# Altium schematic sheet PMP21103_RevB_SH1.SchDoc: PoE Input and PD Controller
size 431 x 279 mm; Date: Not shown in title block; ApprovedBy: Not shown in title block; CheckedBy: Not shown in title block; Author: Not shown in title block; CompanyName: Not shown in title block; Engineer: Not shown in title block; Organization: Not shown in title block; Address1: Not shown in title block; Address2: Not shown in title block; Address3: Not shown in title block; Address4: Not shown in title block; DocumentNumber: 1; Revision: Use project parameter SCH_Rev; SheetNumber: 1; SheetTotal: 3; PageSetup: Record=PageOptions¦CenterHorizontal=True¦CenterVertical=True¦PrintScale=1.00¦XCorrection=1.00¦YCorrection=1.00¦PrintKind=0¦BorderSize=5000000¦LeftOffset=0¦BottomOffset=0¦Orientation=2¦PaperLength=1000¦PaperWidth=1000¦Scale=100¦PaperSource=15¦PrintQuality=600¦MediaType=1¦DitherType=10¦PaperKind=Letter¦PrintScaleMode=1
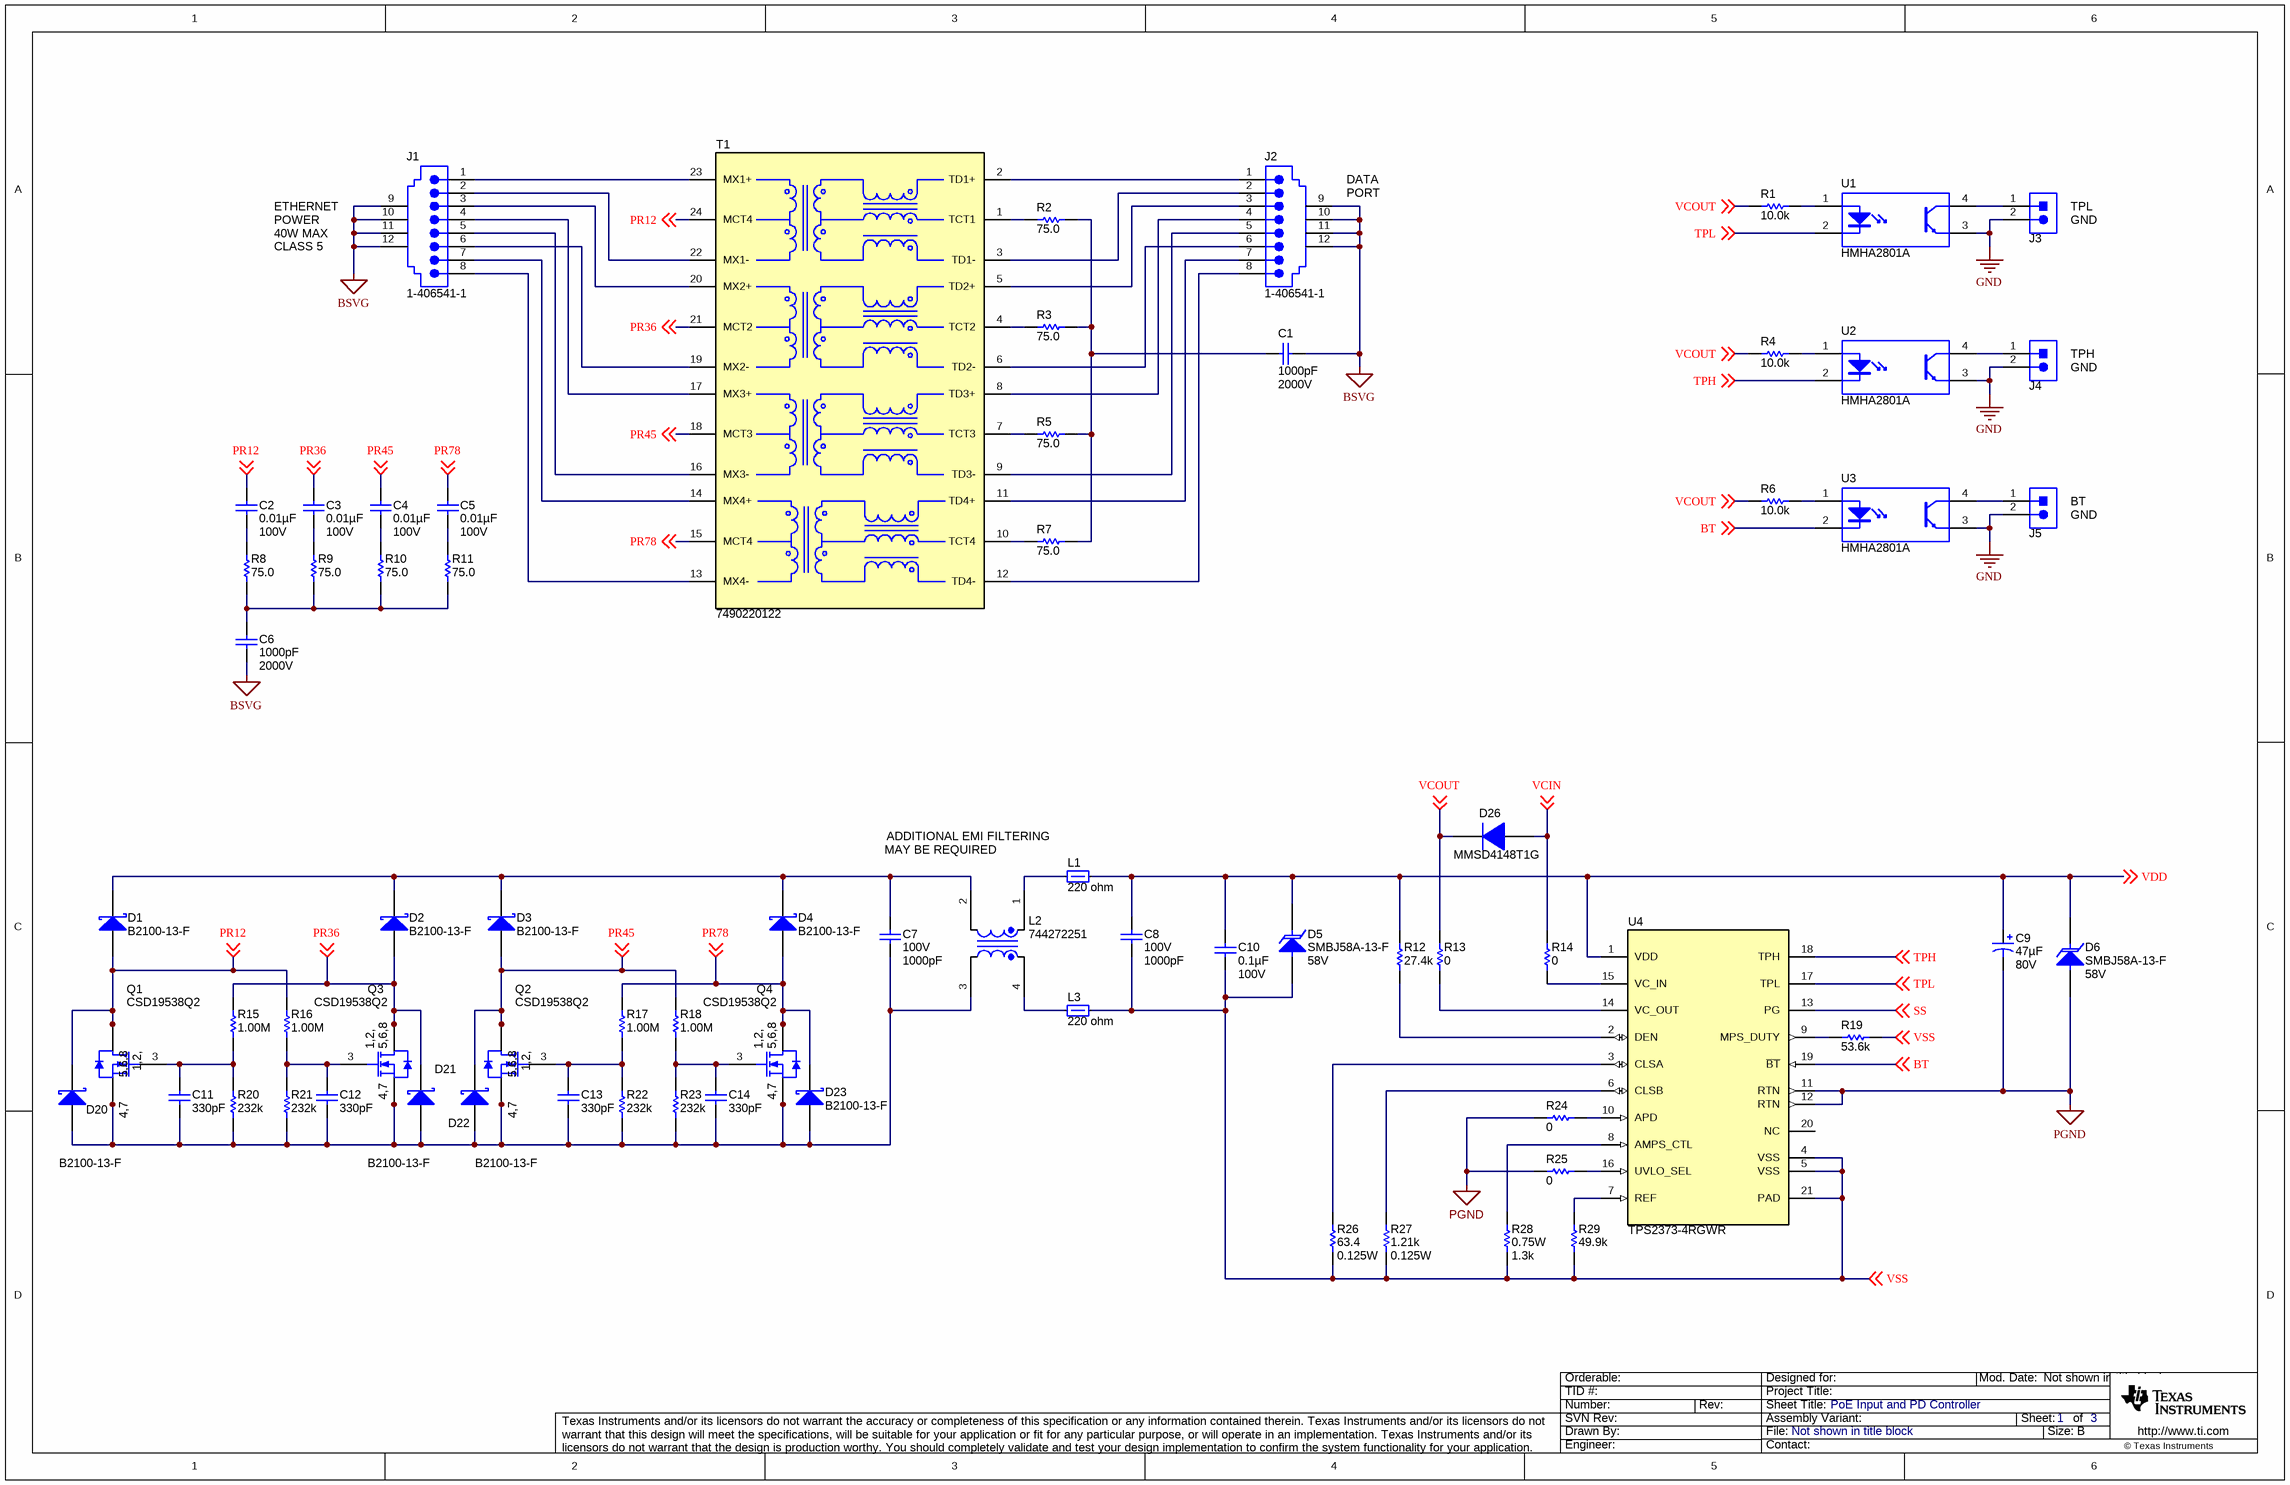
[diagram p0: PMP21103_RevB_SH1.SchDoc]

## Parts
C1  ValueDisplayed: 1000pF  Value2: 2000V  [1812]  (hidden comment: GR443QR73D102KW01L)
C2  ValueDisplayed: 0.01µF  Value2: 100V  [0603L]  (hidden comment: GRM188R72A103KA01D)
C3  ValueDisplayed: 0.01µF  Value2: 100V  [0603L]  (hidden comment: GRM188R72A103KA01D)
C4  ValueDisplayed: 0.01µF  Value2: 100V  [0603L]  (hidden comment: GRM188R72A103KA01D)
C5  ValueDisplayed: 0.01µF  Value2: 100V  [0603L]  (hidden comment: GRM188R72A103KA01D)
C6  ValueDisplayed: 1000pF  Value2: 2000V  [1812]  (hidden comment: GR443QR73D102KW01L)
C7  VDC_V: 100V  ValueDisplayed: 1000pF  [0603]  (hidden comment: GRM188R72A102KA01D)
C8  VDC_V: 100V  ValueDisplayed: 1000pF  [0603]  (hidden comment: GRM188R72A102KA01D)
C9  ValueDisplayed: 47µF  Value2: 80V  [SM_RADIAL_G]  (hidden comment: EEE-FK1K470P)
C10  ValueDisplayed: 0.1µF  Value2: 100V  [0805_HV]  (hidden comment: C2012X7R2A104K125AA)
C11  ValueDisplayed: 330pF  [0603L]  (hidden comment: GRM1885C1H331JA01D)
C12  ValueDisplayed: 330pF  [0603L]  (hidden comment: GRM1885C1H331JA01D)
C13  ValueDisplayed: 330pF  [0603L]  (hidden comment: GRM1885C1H331JA01D)
C14  ValueDisplayed: 330pF  [0603L]  (hidden comment: GRM1885C1H331JA01D)
D1  B2100-13-F  [SMB]
D2  B2100-13-F  [SMB]
D3  B2100-13-F  [SMB]
D4  B2100-13-F  [SMB]
D5  SMBJ58A-13-F  value 58V  [SMB]
D6  SMBJ58A-13-F  value 58V  [SMB]
D20  B2100-13-F  [SMB]
D21  B2100-13-F  [SMB]
D22  B2100-13-F  [SMB]
D23  B2100-13-F  [SMB]
D26  MMSD4148T1G  [SOD-123]
J1  1-406541-1  [TEC_1-406541-1]
J2  1-406541-1  [TEC_1-406541-1]
J3  PEC02SAAN  [CONN_PEC02SAAN]  (value not drawn)
J4  PEC02SAAN  [CONN_PEC02SAAN]  (value not drawn)
J5  PEC02SAAN  [CONN_PEC02SAAN]  (value not drawn)
L1  value 220 ohm  [0603]  (hidden comment: MPZ1608S221A)
L2  744272251  [WE-SL5]
L3  value 220 ohm  [0603]  (hidden comment: MPZ1608S221A)
Q1  CSD19538Q2  [DQK0006C]
Q2  CSD19538Q2  [DQK0006C]
Q3  CSD19538Q2  [DQK0006C]
Q4  CSD19538Q2  [DQK0006C]
R1  ValueDisplayed: 10.0k  [0603L]  (hidden comment: CRCW060310K0FKEA)
R2  value 75.0  [0603L]  (hidden comment: CRCW060375R0FKEA)
R3  value 75.0  [0603L]  (hidden comment: CRCW060375R0FKEA)
R4  ValueDisplayed: 10.0k  [0603L]  (hidden comment: CRCW060310K0FKEA)
R5  value 75.0  [0603L]  (hidden comment: CRCW060375R0FKEA)
R6  ValueDisplayed: 10.0k  [0603L]  (hidden comment: CRCW060310K0FKEA)
R7  value 75.0  [0603L]  (hidden comment: CRCW060375R0FKEA)
R8  value 75.0  [0603L]  (hidden comment: CRCW060375R0FKEA)
R9  value 75.0  [0603L]  (hidden comment: CRCW060375R0FKEA)
R10  value 75.0  [0603L]  (hidden comment: CRCW060375R0FKEA)
R11  value 75.0  [0603L]  (hidden comment: CRCW060375R0FKEA)
R12  ValueDisplayed: 27.4k  [0603L]  (hidden comment: CRCW060327K4FKEA)
R13  ValueDisplayed: 0  [0603L]  (hidden comment: CRCW06030000Z0EA)
R14  ValueDisplayed: 0  [0603L]  (hidden comment: CRCW06030000Z0EA)
R15  ValueDisplayed: 1.00M  [0603L]  (hidden comment: CRCW06031M00FKEA)
R16  ValueDisplayed: 1.00M  [0603L]  (hidden comment: CRCW06031M00FKEA)
R17  ValueDisplayed: 1.00M  [0603L]  (hidden comment: CRCW06031M00FKEA)
R18  ValueDisplayed: 1.00M  [0603L]  (hidden comment: CRCW06031M00FKEA)
R19  ValueDisplayed: 53.6k  [0603L]  (hidden comment: CRCW060353K6FKEA)
R20  ValueDisplayed: 232k  [0603L]  (hidden comment: CRCW0603232KFKEA)
R21  ValueDisplayed: 232k  [0603L]  (hidden comment: CRCW0603232KFKEA)
R22  ValueDisplayed: 232k  [0603L]  (hidden comment: CRCW0603232KFKEA)
R23  ValueDisplayed: 232k  [0603L]  (hidden comment: CRCW0603232KFKEA)
R24  ValueDisplayed: 0  [0603L]  (hidden comment: CRCW06030000Z0EA)
R25  ValueDisplayed: 0  [0603L]  (hidden comment: CRCW06030000Z0EA)
R26  ValueDisplayed: 63.4  Value2: 0.125W  [0805L]  (hidden comment: CRCW080563R4FKEA)
R27  ValueDisplayed: 1.21k  Value2: 0.125W  [0805L]  (hidden comment: CRCW08051K21FKEA)
R28  Value2: 0.75W  ValueDisplayed: 1.3k  [2010]  (hidden comment: CRCW20101K30JNEF)
R29  ValueDisplayed: 49.9k  [0603L]  (hidden comment: CRCW060349K9FKEA)
T1  7490220122  [Wurth_7490220122]
U1  HMHA2801A  [MFP04A]
U2  HMHA2801A  [MFP04A]
U3  HMHA2801A  [MFP04A]
U4  TPS2373-4RGWR  [RGW0020B]

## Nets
BSVG: C1.1 C6.2 J1.9 J1.10 J1.11 J1.12 J2.9 J2.10 J2.11 J2.12
GND: J3.2 J4.2 J5.2 U1.3(E) U2.3(E) U3.3(E)
PGND: C9.2(-) D6.2(A) R24.1 R25.2 U4.11(RTN) U4.12(RTN)
BT: U3.2(K) U4.19(~{BT}) ; off-sheet BT
PR12: C2.1 D1.2(A) D20.1(K) Q1.1(D) Q1.2(D) Q1.5(D) Q1.6(D) Q1.8(D) R16.1 T1.24(MCT4) ; off-sheet PR12
PR36: C3.1 D2.2(A) D21.1(K) Q3.1(D) Q3.2(D) Q3.5(D) Q3.6(D) Q3.8(D) R15.1 T1.21(MCT2) ; off-sheet PR36
PR45: C4.1 D3.2(A) D22.1(K) Q2.1(D) Q2.2(D) Q2.5(D) Q2.6(D) Q2.8(D) R18.1 T1.18(MCT3) ; off-sheet PR45
PR78: C5.1 D4.2(A) D23.1(K) Q4.1(D) Q4.2(D) Q4.5(D) Q4.6(D) Q4.8(D) R17.1 T1.15(MCT4) ; off-sheet PR78
SS: U4.13(PG) ; off-sheet SS
TPH: U2.2(K) U4.18(TPH) ; off-sheet TPH
TPL: U1.2(K) U4.17(TPL) ; off-sheet TPL
VCIN: D26.2(A) R14.2 ; off-sheet VCIN
VCOUT: D26.1(K) R1.1 R4.1 R6.1 R13.2 ; off-sheet VCOUT
VDD: C8.1 C9.1(+) C10.2 D5.1(K) D6.1(K) L1.2 R12.2 U4.1(VDD) ; off-sheet VDD
VSS: C8.2 C10.1 D5.2(A) L3.2 R19.2 R26.1 R27.1 R28.1 R29.1 U4.4(VSS) U4.5(VSS) U4.21(PAD) ; off-sheet VSS
NetC1_2: C1.2 R2.1 R3.1 R5.1 R7.1
NetC2_2: C2.2 R8.2
NetC3_2: C3.2 R9.2
NetC4_2: C4.2 R10.2
NetC5_2: C5.2 R11.2
NetC6_1: C6.1 R8.1 R9.1 R10.1 R11.1
NetC7_1: C7.1 D1.1(K) D2.1(K) D3.1(K) D4.1(K) L2.2
NetC7_2: C7.2 C11.2 C12.2 C13.2 C14.2 D20.2(A) D21.2(A) D22.2(A) D23.2(A) L2.3 Q1.4(S) Q1.7(S) Q2.4(S) Q2.7(S) Q3.4(S) Q3.7(S) Q4.4(S) Q4.7(S) R20.1 R21.1 R22.1 R23.1
NetC11_1: C11.1 Q1.3(G) R15.2 R20.2
NetC12_1: C12.1 Q3.3(G) R16.2 R21.2
NetC13_1: C13.1 Q2.3(G) R17.2 R22.2
NetC14_1: C14.1 Q4.3(G) R18.2 R23.2
NetJ1_1: J1.1 T1.23(MX1+)
NetJ1_2: J1.2 T1.22(MX1-)
NetJ1_3: J1.3 T1.20(MX2+)
NetJ1_4: J1.4 T1.17(MX3+)
NetJ1_5: J1.5 T1.16(MX3-)
NetJ1_6: J1.6 T1.19(MX2-)
NetJ1_7: J1.7 T1.14(MX4+)
NetJ1_8: J1.8 T1.13(MX4-)
NetJ2_1: J2.1 T1.2(TD1+)
NetJ2_2: J2.2 T1.3(TD1-)
NetJ2_3: J2.3 T1.5(TD2+)
NetJ2_4: J2.4 T1.8(TD3+)
NetJ2_5: J2.5 T1.9(TD3-)
NetJ2_6: J2.6 T1.6(TD2-)
NetJ2_7: J2.7 T1.11(TD4+)
NetJ2_8: J2.8 T1.12(TD4-)
NetJ3_1: J3.1 U1.4(C)
NetJ4_1: J4.1 U2.4(C)
NetJ5_1: J5.1 U3.4(C)
NetL1_1: L1.1 L2.1
NetL2_4: L2.4 L3.1
NetR1_2: R1.2 U1.1(A)
NetR2_2: R2.2 T1.1(TCT1)
NetR3_2: R3.2 T1.4(TCT2)
NetR4_2: R4.2 U2.1(A)
NetR5_2: R5.2 T1.7(TCT3)
NetR6_2: R6.2 U3.1(A)
NetR7_2: R7.2 T1.10(TCT4)
NetR12_1: R12.1 U4.2(DEN)
NetR13_1: R13.1 U4.14(VC_OUT)
NetR14_1: R14.1 U4.15(VC_IN)
NetR19_1: R19.1 U4.9(MPS_DUTY)
NetR24_2: R24.2 U4.10(APD)
NetR25_1: R25.1 U4.16(UVLO_SEL)
NetR26_2: R26.2 U4.3(CLSA)
NetR27_2: R27.2 U4.6(CLSB)
NetR28_2: R28.2 U4.8(AMPS_CTL)
NetR29_2: R29.2 U4.7(REF)

Not connected (* = marked no-connect by the designer): U4 20(NC)

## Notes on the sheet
- ETHERNET
- 40W MAX
- POWER
- (near J2) DATA
- (near J2) PORT
- (near J3) TPL
- (near J3) GND
- CLASS 5
- (near J4) TPH
- (near J4) GND
- (near J5) BT
- (near J5) GND
- (near L1) ADDITIONAL EMI FILTERING
- MAY BE REQUIRED

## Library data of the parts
C1 C6 = GR443QR73D102KW01L: CAP, CERM, 1000 pF, 2000 V, +/- 10%, X7R, 1812; Manufacturer: MuRata; Polarized: N; CompType: Capacitor; Value: 1000pF; U/M: EA; Cap_F: 0.000000001; Tolerance_%: 10; Value1: Unknown; VDC_V: 2000; TaMin_C: -55; TaMax_C: 125; SizeArea_mm2: 14.4; SizeAreaWB_mm2: 23.1; SizeX_mm: 4.5; SizeY_mm: 3.2; SizeZ_mm: 1.35; AEC Category: Q200
C2-C5 = GRM188R72A103KA01D: CAP, CERM, 0.01 µF, 100 V, +/- 10%, X7R, 0603; Manufacturer: MuRata; Polarized: N; CompType: Capacitor; Value: 0.01uF; U/M: EA; Cap_F: 0.00000001; Tolerance_%: 10; Value1: Unknown; VDC_V: 100; TaMin_C: -55; TaMax_C: 125; Cap_Case: 0603; SizeArea_mm2: 1.28; SizeAreaWB_mm2: 4.68; SizeX_mm: 1.6; SizeY_mm: 0.8; SizeZ_mm: 1; AEC Category: Q200
C7 C8 = CMP-0007467-2: CAP, CERM, 1000 pF, 100 V, +/- 10%, X7R, 0603; Manufacturer: MuRata; TaMin_C: -55°C; Polarized: N; SizeAreaWB_mm2: 4.68; Value1: Unknown; U/M: EA; Value: 1000pF; TaMax_C: 125°C; SizeZ_mm: 1; SizeX_mm: 1.6; SizeY_mm: 0.8; SizeArea_mm2: 1.28; Cap_F: 1nF; AEC Category: Q200
C9 = EEE-FK1K470P: CAP, AL, 47 µF, 80 V, +/- 20%, 0.7 ohm, AEC-Q200 Grade 2, SMD; Manufacturer: Panasonic; Polarized: Y; CompType: Capacitor; Value: 47uF; U/M: EA; Cap_F: 0.000047; Tolerance_%: 20; Value1: 0.7 ohm; VDC_V: 80; ESR_ohm: 0.7; IRMS_A: 0.2; TaMin_C: -55; TaMax_C: 105; Cap_Case: G; AEC Category: Q200; AEC Grade: 2; SizeAreaWB_mm2: 172.2; SizeArea_mm2: 123.6; SizeX_mm: 12; SizeY_mm: 10.3; SizeZ_mm: 10.2
C10 = C2012X7R2A104K125AA: CAP, CERM, 0.1 µF, 100 V, +/- 10%, X7R, 0805; Manufacturer: TDK; Polarized: N; CompType: Capacitor; Value: 0.1uF; U/M: EA; Cap_F: 0.0000001; Tolerance_%: 10; ESR_ohm: 0.020726; Value1: 0.020726 ohm; VDC_V: 100; IRMS_A: 1.456; TaMin_C: -55; TaMax_C: 125; Cap_Case: 0805; SizeArea_mm2: 2.5; SizeAreaWB_mm2: 6.75; SizeX_mm: 2; SizeY_mm: 1.25; SizeZ_mm: 1.45; AEC Category: Q200
C11-C14 = GRM1885C1H331JA01D: CAP, CERM, 330 pF, 50 V, +/- 5%, C0G/NP0, 0603; Manufacturer: MuRata; Polarized: N; CompType: Capacitor; Value: 330pF; U/M: EA; Cap_F: 0.00000000033; Tolerance_%: 5; Value1: Unknown; VDC_V: 50; Value2: 50V; TaMin_C: -55; TaMax_C: 125; Cap_Case: 0603; SizeArea_mm2: 1.28; SizeAreaWB_mm2: 4.68; SizeX_mm: 1.6; SizeY_mm: 0.8; SizeZ_mm: 1; AEC Category: Q200
D1-D4 = B2100-13-F: Diode, Schottky, 100V, 2A, SMB; Manufacturer: Diodes Inc.; U/M: EA; Vf_V: 0.79; Value2: 0.79V; Io_A: 2; Vr_V: 100; TJmax_C: 150; RJC_CperW: 15
D5 D6 = SMBJ58A-13-F: Diode, TVS, Uni, 58V, 600W, SMB; Manufacturer: Diodes Inc.; U/M: EA; Power_W: 5; Vr_V: 58; Value1: 5W
D20-D23 = CMP-0028397-2: Diode, Schottky, 100 V, 2 A, SMB; Manufacturer: Diodes Inc.; Value2: 0.79V; Value1: 2A; SizeArea_mm2: 21.336; Value: 100V; Green_REACh: Passed; Green_Lifecycle: Active; Vf_V: 790mV; SizeY_mm: 3.81; AEC Category: Q101; SizeZ_mm: 2.6; TJmax_C: 150°C; RJC_CperW: 15; SizeAreaWB_mm2: 44.156; SizeX_mm: 5.6
D26 = CMP-0029032-2: Diode, Switching, 100 V, 0.2 A, SOD-123; Manufacturer: ON Semiconductor; Value: 100V; SizeY_mm: 1.7; Io_A: 200mA; SizeAreaWB_mm2: 13.095; SizeArea_mm2: 6.545; Vf_V: 1V; TJmax_C: 150°C; SizeX_mm: 3.85; SizeZ_mm: 1.35; Value1: 0.2A; Green_Lifecycle: Active; AEC Category: Q101; Green_REACh: Passed
J1 J2 = 1-406541-1: RJ-45, Right Angle, No LED, tab up; Manufacturer: AMP; SymbolCreator: x0208326; CompType: Connector; U/M: EA; Note: updated F/S per request.  Made footprint to max size.  2103-11-27
J3-J5 = PEC02SAAN: Header, 100mil, 2x1, Tin, TH; Manufacturer: Sullins Connector Solutions; SymbolCreator: a0412235; U/M: EA
L1 L3 = MPZ1608S221A: Ferrite Bead, 220 ohm @ 100 MHz, 2.2 A, 0603; Manufacturer: TDK; Imax_A: 2.2; DCR_ohm: 0.05; Value1: 0.05 ohm; Value2: 2.2A; ZTyp@100MHz_Ohm: 220
L2 = 744272251: Coupled inductor, 250 µH,  A, 0.035 ohm, SMD; Manufacturer: Wurth Elektronik; SymbolCreator: a0412235; ValueDisplayed: 250µH; Value: 250uH; Ind_H: 250.0E-6; DCR_ohm: 0.035
Q1-Q4 = CSD19538Q2: MOSFET, N-CH, 100 V, 4.5 A, DQK0006C (WSON-6); Manufacturer: Texas Instruments; Alternate Manufacturer: None; U/M: EA; ChType: N; Value: 100V; VdsMax_V: 100; Value1: ? ohm; Value2: ? nC; Vgs_V: 20; IdsMax_A: 4.5; SizeAreaWB_mm2: 9; SizeArea_mm2: 4; SizeX_mm: 2; SizeZ_mm: 0.8; AEC Category: Q101
R1 R4 R6 = CRCW060310K0FKEA: RES, 10.0 k, 1%, 0.1 W, 0603; Manufacturer: Vishay-Dale; CompType: Resistor; Value: 10.0k; Res_ohm: 10000; Value_Code: 10k0; Tolerance_%: 1; Power_W: 0.1; Value2: 0.1W; VDC_V: 75; TempCo: 100 ppm/C; EIA_Code: E96; U/M: EA
R2 R3 R5 R7-R11 = CRCW060375R0FKEA: RES, 75.0 ohm, 1%, 0.1W, 0603; Manufacturer: Vishay-Dale; CompType: Resistor; Res_ohm: 75; Value_Code: 75R0; Tolerance_%: 1; Power_W: 0.1; TempCo: 100 ppm/C; EIA_Code: E96; U/M: EA
R12 = CRCW060327K4FKEA: RES, 27.4 k, 1%, 0.1 W, 0603; Manufacturer: Vishay-Dale; CompType: Resistor; Value: 27.4k; Res_ohm: 27400; Value_Code: 27k4; Tolerance_%: 1; Power_W: 0.1; Value2: 0.1W; VDC_V: 75; TempCo: 100 ppm/C; EIA_Code: E96; U/M: EA; SizeArea_mm2: 1.28; SizeX_mm: 1.6; SizeY_mm: 0.8; AEC Category: Q200; Green_Lifecycle: Active; Green_REACh: Passed
R13 R14 R24 R25 = CRCW06030000Z0EA: RES, 0, 5%, 0.1 W, 0603; Manufacturer: Vishay-Dale; CompType: Resistor; Value: 0; Value_Code: 0000; Tolerance_%: 5; Power_W: 0.1; Value2: 0.1W; VDC_V: 75; TempCo: 200 ppm/C; SizeArea_mm2: 1.28; SizeX_mm: 1.6; SizeY_mm: 0.8; SizeZ_mm: 1; EIA_Code: E24; U/M: EA; AEC Category: Q200
R15-R18 = CRCW06031M00FKEA: RES, 1.00 M, 1%, 0.1 W, 0603; Manufacturer: Vishay-Dale; CompType: Resistor; Value: 1.00Meg; Res_ohm: 1000000; Value_Code: 1M00; Tolerance_%: 1; Power_W: 0.1; Value2: 0.1W; VDC_V: 75; TempCo: 100 ppm/C; EIA_Code: E96; U/M: EA; SizeArea_mm2: 1.28; SizeX_mm: 1.6; SizeY_mm: 0.8; AEC Category: Q200
R19 = CRCW060353K6FKEA: RES, 53.6 k, 1%, 0.1 W, 0603; Manufacturer: Vishay-Dale; CompType: Resistor; Value: 53.6k; Res_ohm: 53600; Value_Code: 53k6; Tolerance_%: 1; Power_W: 0.1; Value2: 0.1W; VDC_V: 75; TempCo: 100 ppm/C; EIA_Code: E96; U/M: EA; AEC Category: Q200
R20-R23 = CRCW0603232KFKEA: RES, 232 k, 1%, 0.1 W, 0603; Manufacturer: Vishay-Dale; CompType: Resistor; Value: 232k; Res_ohm: 232000; Tolerance_%: 1; Power_W: 0.1; Value2: 0.1W; VDC_V: 75; TempCo: 100 ppm/C; EIA_Code: E96; U/M: EA; SizeArea_mm2: 1.28; SizeX_mm: 1.6; SizeY_mm: 0.8; AEC Category: Q200
R26 = CRCW080563R4FKEA: RES, 63.4, 1%, 0.125 W, 0805; Manufacturer: Vishay-Dale; CompType: Resistor; Value: 63.4; Value_Code: 63R4; Tolerance_%: 1; Power_W: 0.125; VDC_V: 150; TempCo: 100 ppm/C; EIA_Code: E96; U/M: EA
R27 = CRCW08051K21FKEA: RES, 1.21 k, 1%, 0.125 W, 0805; Manufacturer: Vishay-Dale; CompType: Resistor; Value: 1.21k; Res_ohm: 1210; Value_Code: 1k21; Tolerance_%: 1; Power_W: 0.125; VDC_V: 150; TempCo: 100 ppm/C; EIA_Code: E96; U/M: EA; SizeArea_mm2: 2.5; SizeX_mm: 2; SizeY_mm: 1.25; SizeZ_mm: 1.45; AEC Category: Q200
R28 = CMP-0016077-3: RES, 1.3 k, 5%, 0.75 W, AEC-Q200 Grade 0, 2010; Manufacturer: Vishay-Dale; Power_W: 750mW; TempCo: 200 ppm/C; Value_Code: 1k30; Value: 1.3k; EIA_Code: E24; SizeX_mm: 5; SizeY_mm: 2.5; SizeZ_mm: 1.66; SizeArea_mm2: 12.5; CompType: Resistor; AEC Qualified: Y; VDC_V: 400V; AEC Grade: 0; AEC Category: Q200
R29 = CRCW060349K9FKEA: RES, 49.9 k, 1%, 0.1 W, 0603; Manufacturer: Vishay-Dale; CompType: Resistor; Value: 49.9k; Res_ohm: 49900; Value_Code: 49k9; Tolerance_%: 1; Power_W: 0.1; Value2: 0.1W; VDC_V: 75; TempCo: 100 ppm/C; EIA_Code: E96; U/M: EA; AEC Category: Q200
T1 = 7490220122: Transformer, 350 uH, SMT; Manufacturer: Wurth Elektronik; SymbolCreator: Altium; ValueDisplayed: 350µH; Value: 350uH; Lp: 350
U1-U3 = HMHA2801A: Optocoupler, 3.75 kV, 80-160% CTR, SMT; Manufacturer: Fairchild Semiconductor; CTR (Min): 80%; CTR (Max): 160%; Voltage_Isolation_Vrms: 3750V; SizeAreaWB_mm2: 4; SizeArea_mm2: 1
U4 = TPS2373-4RGWR: High-Power PoE PD Interface with Advanced Startup, RGW0020B (VQFN-20); Alternate PartNumber: TPS2373-4RGWT; Manufacturer: Texas Instruments; SymbolCreator: Altium; SizeArea_mm2: 25; SizeAreaWB_mm2: 49; SizeX_mm: 5; SizeZ_mm: 1; CompType: IC; U/M: EA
